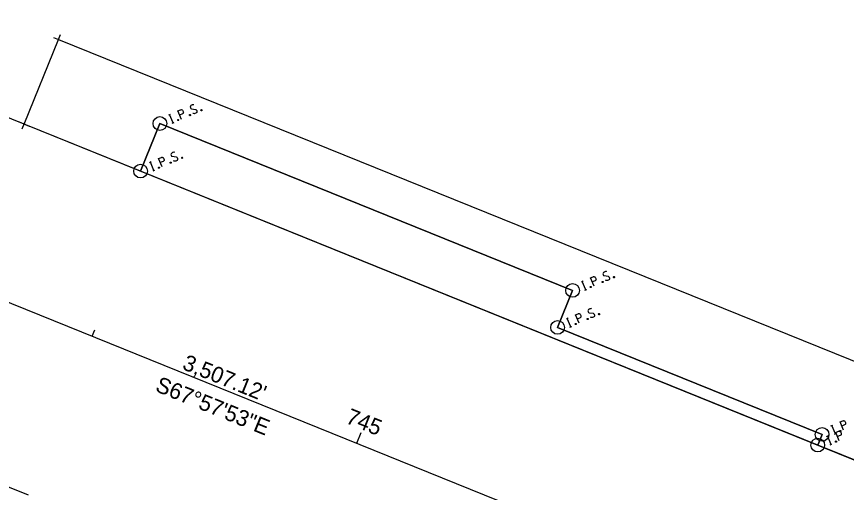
# Model space of a CAD drawing. Extents: x 2345526 to 2352057, y 624934 to 629976.
# Drawn here: x 2347207 to 2347352.4, y 627495.5 to 627578.9 of the extents above; entities that cross this region are included whole.
import ezdxf

# ---------------------------------------------------------------- set-up
doc = ezdxf.new("R2010")
doc.units = 0
for name, color, linetype in [('DT_X_Island', 7, 'Continuous'), ('DT_X_TIN_Hull', 7, 'Continuous'), ('DT_X_Void', 7, 'Continuous'), ('DV_X_Property_Line', 7, 'Continuous'), ('RW_P_Esmt_SH', 7, 'Continuous'), ('RW_X_CL', 7, 'Continuous'), ('RW_X_CL_1000_Stations', 7, 'Continuous'), ('RW_X_CL_100_Cardinal_Points', 7, 'Continuous'), ('RW_X_CL_100_Distances', 7, 'Continuous'), ('RW_X_CL_100_Stations', 7, 'Continuous'), ('RW_X_CL_500_Cardinal_Points', 7, 'Continuous'), ('RW_X_Esmt_SH', 7, 'Continuous'), ('SC_Scratch1', 7, 'Continuous')]:
    doc.layers.add(name, color=color, linetype=linetype)

msp = doc.modelspace()

# ---------------------------------------------------------------- linework, layer by layer
at = {"layer": 'DT_X_Island'}
for p, q in [((2347228.77, 627551.81), (2347232.14, 627560.15)), ((2347232.14, 627560.15), (2347304.45, 627530.89)), ((2347347.42, 627503.78), (2347228.77, 627551.81)), ((2347304.45, 627530.89), (2347301.82, 627524.4)), ((2347301.82, 627524.4), (2347348.17, 627505.64)), ((2347348.17, 627505.64), (2347347.42, 627503.78))]:
    msp.add_line(p, q, dxfattribs=at)
at = {"layer": 'DT_X_TIN_Hull'}
for p, q in [((2347214.02, 627574.02), (2347214.73, 627575.77)), ((2347208.37, 627560.06), (2347214.38, 627574.89)), ((2347213.5, 627575.25), (2347215.25, 627574.54)), ((2347214.38, 627574.89), (2347372.89, 627510.74)), ((2347208.02, 627559.19), (2347208.73, 627560.94)), ((2347207.5, 627560.42), (2347209.25, 627559.71)), ((2347228.77, 627551.81), (2347208.37, 627560.06)), ((2347232.14, 627560.15), (2347228.77, 627551.81)), ((2347304.45, 627530.89), (2347232.14, 627560.15)), ((2347301.82, 627524.4), (2347304.45, 627530.89)), ((2347134.88, 627525.08), (2347209.04, 627495.06)), ((2347348.17, 627505.64), (2347301.82, 627524.4)), ((2347347.42, 627503.78), (2347348.17, 627505.64)), ((2347366.88, 627495.91), (2347347.42, 627503.78))]:
    msp.add_line(p, q, dxfattribs=at)
at = {"layer": 'DT_X_Void'}
for points in [[(2347235.92, 627560.88), (2347235.29, 627562.36), (2347235.78, 627562.56), (2347235.84, 627562.57), (2347235.92, 627562.58), (2347235.96, 627562.57), (2347236, 627562.56), (2347236.06, 627562.52), (2347236.12, 627562.47), (2347236.18, 627562.39), (2347236.24, 627562.25), (2347236.25, 627562.2), (2347236.26, 627562.12), (2347236.25, 627562.02), (2347236.22, 627561.97), (2347236.2, 627561.93), (2347236.16, 627561.89), (2347236.09, 627561.84), (2347235.6, 627561.64)], [(2347238.11, 627563.42), (2347238.08, 627563.44), (2347238.04, 627563.45), (2347237.93, 627563.45), (2347237.81, 627563.42), (2347237.73, 627563.39), (2347237.7, 627563.37), (2347237.58, 627563.28), (2347237.5, 627563.17), (2347237.47, 627563.04), (2347237.49, 627562.94), (2347237.52, 627562.87), (2347237.58, 627562.79), (2347237.69, 627562.74), (2347238.4, 627562.63), (2347238.47, 627562.61), (2347238.51, 627562.57), (2347238.56, 627562.51), (2347238.59, 627562.44), (2347238.61, 627562.36), (2347238.62, 627562.31), (2347238.62, 627562.25), (2347238.62, 627562.19), (2347238.61, 627562.15), (2347238.6, 627562.1), (2347238.58, 627562.06), (2347238.55, 627562.02), (2347238.52, 627562), (2347238.44, 627561.95), (2347238.29, 627561.89), (2347238.19, 627561.87), (2347238.03, 627561.9), (2347237.91, 627561.93)], [(2347239.36, 627562.57), (2347239.41, 627562.59), (2347239.45, 627562.58), (2347239.5, 627562.55), (2347239.52, 627562.49), (2347239.51, 627562.43), (2347239.49, 627562.4), (2347239.44, 627562.37), (2347239.4, 627562.38), (2347239.35, 627562.42), (2347239.33, 627562.48), (2347239.34, 627562.54), (2347239.36, 627562.57)], [(2347233.69, 627561.68), (2347234.02, 627561.81)], [(2347234.48, 627560.27), (2347233.85, 627561.74)], [(2347235.28, 627560.84), (2347235.33, 627560.86), (2347235.37, 627560.85), (2347235.42, 627560.82), (2347235.44, 627560.76), (2347235.43, 627560.7), (2347235.41, 627560.67), (2347235.36, 627560.65), (2347235.32, 627560.66), (2347235.27, 627560.69), (2347235.25, 627560.75), (2347235.26, 627560.81), (2347235.28, 627560.84)], [(2347237.35, 627561.72), (2347237.4, 627561.74), (2347237.44, 627561.73), (2347237.49, 627561.7), (2347237.51, 627561.64), (2347237.5, 627561.58), (2347237.48, 627561.54), (2347237.43, 627561.52), (2347237.39, 627561.53), (2347237.34, 627561.57), (2347237.32, 627561.62), (2347237.33, 627561.68), (2347237.35, 627561.72)], [(2347234.31, 627560.2), (2347234.64, 627560.34)], [(2347234.73, 627555.08), (2347234.7, 627555.1), (2347234.66, 627555.11), (2347234.56, 627555.1), (2347234.43, 627555.08), (2347234.35, 627555.04), (2347234.32, 627555.03), (2347234.21, 627554.94), (2347234.12, 627554.82), (2347234.09, 627554.7), (2347234.11, 627554.6), (2347234.14, 627554.53), (2347234.2, 627554.45), (2347234.32, 627554.4), (2347235.02, 627554.29), (2347235.09, 627554.26), (2347235.13, 627554.23), (2347235.18, 627554.16), (2347235.21, 627554.09), (2347235.23, 627554.02), (2347235.24, 627553.97), (2347235.24, 627553.9), (2347235.24, 627553.85), (2347235.24, 627553.81), (2347235.22, 627553.76), (2347235.2, 627553.72), (2347235.17, 627553.68), (2347235.15, 627553.66), (2347235.06, 627553.61), (2347234.92, 627553.55), (2347234.82, 627553.53), (2347234.65, 627553.56), (2347234.54, 627553.59)], [(2347230.31, 627553.33), (2347230.64, 627553.47)], [(2347232.54, 627552.54), (2347231.92, 627554.01), (2347232.4, 627554.22), (2347232.46, 627554.23), (2347232.54, 627554.24), (2347232.58, 627554.23), (2347232.62, 627554.22), (2347232.69, 627554.17), (2347232.74, 627554.13), (2347232.8, 627554.05), (2347232.86, 627553.91), (2347232.87, 627553.86), (2347232.88, 627553.78), (2347232.87, 627553.68), (2347232.85, 627553.63), (2347232.83, 627553.59), (2347232.79, 627553.55), (2347232.71, 627553.5), (2347232.22, 627553.29)], [(2347235.98, 627554.23), (2347236.03, 627554.25), (2347236.07, 627554.24), (2347236.12, 627554.21), (2347236.15, 627554.15), (2347236.13, 627554.09), (2347236.11, 627554.05), (2347236.06, 627554.03), (2347236.02, 627554.04), (2347235.97, 627554.08), (2347235.95, 627554.13), (2347235.96, 627554.19), (2347235.98, 627554.23)], [(2347231.1, 627551.93), (2347230.48, 627553.4)], [(2347231.9, 627552.5), (2347231.95, 627552.52), (2347231.99, 627552.51), (2347232.04, 627552.48), (2347232.07, 627552.42), (2347232.05, 627552.36), (2347232.03, 627552.32), (2347231.98, 627552.3), (2347231.94, 627552.31), (2347231.89, 627552.35), (2347231.87, 627552.4), (2347231.88, 627552.46), (2347231.9, 627552.5)], [(2347233.97, 627553.38), (2347234.02, 627553.4), (2347234.06, 627553.39), (2347234.11, 627553.36), (2347234.14, 627553.3), (2347234.13, 627553.24), (2347234.1, 627553.2), (2347234.05, 627553.18), (2347234.01, 627553.19), (2347233.96, 627553.22), (2347233.94, 627553.28), (2347233.95, 627553.34), (2347233.97, 627553.38)], [(2347230.94, 627551.86), (2347231.26, 627552)], [(2347308.22, 627531.62), (2347307.6, 627533.09), (2347308.08, 627533.3), (2347308.14, 627533.31), (2347308.22, 627533.31), (2347308.26, 627533.3), (2347308.3, 627533.29), (2347308.37, 627533.25), (2347308.42, 627533.21), (2347308.48, 627533.12), (2347308.54, 627532.98), (2347308.55, 627532.93), (2347308.56, 627532.86), (2347308.55, 627532.76), (2347308.53, 627532.71), (2347308.51, 627532.67), (2347308.46, 627532.62), (2347308.39, 627532.58), (2347307.9, 627532.37)], [(2347310.41, 627534.16), (2347310.38, 627534.18), (2347310.34, 627534.19), (2347310.23, 627534.18), (2347310.11, 627534.16), (2347310.03, 627534.12), (2347310, 627534.11), (2347309.88, 627534.02), (2347309.8, 627533.9), (2347309.77, 627533.78), (2347309.79, 627533.68), (2347309.82, 627533.61), (2347309.88, 627533.52), (2347309.99, 627533.48), (2347310.7, 627533.37), (2347310.77, 627533.34), (2347310.81, 627533.3), (2347310.86, 627533.24), (2347310.89, 627533.17), (2347310.91, 627533.1), (2347310.92, 627533.05), (2347310.92, 627532.98), (2347310.92, 627532.93), (2347310.92, 627532.88), (2347310.9, 627532.84), (2347310.88, 627532.8), (2347310.85, 627532.76), (2347310.82, 627532.74), (2347310.74, 627532.68), (2347310.6, 627532.62), (2347310.49, 627532.61), (2347310.33, 627532.63), (2347310.22, 627532.67)], [(2347311.66, 627533.31), (2347311.71, 627533.33), (2347311.75, 627533.32), (2347311.8, 627533.29), (2347311.82, 627533.23), (2347311.81, 627533.17), (2347311.79, 627533.13), (2347311.74, 627533.11), (2347311.7, 627533.12), (2347311.65, 627533.15), (2347311.63, 627533.21), (2347311.64, 627533.27), (2347311.66, 627533.31)], [(2347305.99, 627532.41), (2347306.32, 627532.55)], [(2347306.78, 627531.01), (2347306.16, 627532.48)], [(2347309.65, 627532.46), (2347309.7, 627532.48), (2347309.74, 627532.47), (2347309.79, 627532.43), (2347309.81, 627532.38), (2347309.8, 627532.32), (2347309.78, 627532.28), (2347309.73, 627532.26), (2347309.69, 627532.27), (2347309.64, 627532.3), (2347309.62, 627532.36), (2347309.63, 627532.42), (2347309.65, 627532.46)], [(2347306.62, 627530.94), (2347306.94, 627531.08)], [(2347307.58, 627531.58), (2347307.63, 627531.6), (2347307.67, 627531.59), (2347307.72, 627531.56), (2347307.74, 627531.5), (2347307.73, 627531.44), (2347307.71, 627531.4), (2347307.66, 627531.38), (2347307.62, 627531.39), (2347307.57, 627531.43), (2347307.55, 627531.48), (2347307.56, 627531.54), (2347307.58, 627531.58)], [(2347307.79, 627527.67), (2347307.76, 627527.69), (2347307.71, 627527.7), (2347307.61, 627527.69), (2347307.49, 627527.67), (2347307.41, 627527.63), (2347307.38, 627527.62), (2347307.26, 627527.53), (2347307.18, 627527.41), (2347307.14, 627527.29), (2347307.16, 627527.19), (2347307.19, 627527.12), (2347307.25, 627527.04), (2347307.37, 627526.99), (2347308.07, 627526.88), (2347308.14, 627526.85), (2347308.18, 627526.82), (2347308.23, 627526.75), (2347308.26, 627526.68), (2347308.28, 627526.61), (2347308.29, 627526.56), (2347308.3, 627526.49), (2347308.3, 627526.44), (2347308.29, 627526.4), (2347308.27, 627526.35), (2347308.25, 627526.31), (2347308.22, 627526.27), (2347308.2, 627526.25), (2347308.11, 627526.2), (2347307.97, 627526.14), (2347307.87, 627526.12), (2347307.7, 627526.15), (2347307.59, 627526.18)], [(2347303.37, 627525.92), (2347303.69, 627526.06)], [(2347304.15, 627524.52), (2347303.53, 627525.99)], [(2347305.59, 627525.13), (2347304.97, 627526.6), (2347305.46, 627526.81), (2347305.51, 627526.82), (2347305.59, 627526.83), (2347305.63, 627526.82), (2347305.67, 627526.81), (2347305.74, 627526.76), (2347305.79, 627526.72), (2347305.85, 627526.64), (2347305.91, 627526.5), (2347305.92, 627526.45), (2347305.93, 627526.37), (2347305.93, 627526.27), (2347305.9, 627526.22), (2347305.88, 627526.18), (2347305.84, 627526.14), (2347305.76, 627526.09), (2347305.27, 627525.88)], [(2347307.02, 627525.97), (2347307.07, 627525.99), (2347307.11, 627525.98), (2347307.16, 627525.95), (2347307.19, 627525.89), (2347307.18, 627525.83), (2347307.16, 627525.79), (2347307.11, 627525.77), (2347307.07, 627525.78), (2347307.02, 627525.81), (2347306.99, 627525.87), (2347307, 627525.93), (2347307.02, 627525.97)], [(2347309.03, 627526.82), (2347309.08, 627526.84), (2347309.12, 627526.83), (2347309.17, 627526.8), (2347309.2, 627526.74), (2347309.19, 627526.68), (2347309.17, 627526.64), (2347309.12, 627526.62), (2347309.08, 627526.63), (2347309.03, 627526.67), (2347309, 627526.72), (2347309.01, 627526.78), (2347309.03, 627526.82)], [(2347303.99, 627524.45), (2347304.32, 627524.59)], [(2347304.95, 627525.09), (2347305, 627525.11), (2347305.04, 627525.1), (2347305.09, 627525.07), (2347305.12, 627525.01), (2347305.11, 627524.95), (2347305.09, 627524.91), (2347305.04, 627524.89), (2347305, 627524.9), (2347304.95, 627524.94), (2347304.92, 627524.99), (2347304.93, 627525.05), (2347304.95, 627525.09)], [(2347349.71, 627507.16), (2347350.04, 627507.3)], [(2347350.5, 627505.76), (2347349.88, 627507.23)], [(2347351.94, 627506.37), (2347351.32, 627507.84), (2347351.8, 627508.05), (2347351.86, 627508.06), (2347351.94, 627508.07), (2347351.98, 627508.06), (2347352.02, 627508.05), (2347352.09, 627508.01), (2347352.14, 627507.96), (2347352.2, 627507.88), (2347352.26, 627507.74), (2347352.27, 627507.69), (2347352.28, 627507.61), (2347352.27, 627507.51), (2347352.25, 627507.46), (2347352.23, 627507.42), (2347352.19, 627507.38), (2347352.11, 627507.33), (2347351.62, 627507.12)], [(2347350.34, 627505.69), (2347350.66, 627505.83)], [(2347351.19, 627504.52), (2347350.57, 627505.99), (2347351.05, 627506.2), (2347351.11, 627506.21), (2347351.19, 627506.21), (2347351.23, 627506.2), (2347351.27, 627506.19), (2347351.34, 627506.15), (2347351.39, 627506.11), (2347351.45, 627506.02), (2347351.51, 627505.88), (2347351.52, 627505.83), (2347351.53, 627505.75), (2347351.52, 627505.66), (2347351.5, 627505.6), (2347351.48, 627505.57), (2347351.44, 627505.52), (2347351.36, 627505.48), (2347350.87, 627505.27)], [(2347351.3, 627506.33), (2347351.35, 627506.35), (2347351.39, 627506.34), (2347351.44, 627506.31), (2347351.47, 627506.25), (2347351.46, 627506.19), (2347351.43, 627506.16), (2347351.38, 627506.13), (2347351.34, 627506.14), (2347351.29, 627506.18), (2347351.27, 627506.24), (2347351.28, 627506.3), (2347351.3, 627506.33)], [(2347348.96, 627505.31), (2347349.29, 627505.45)], [(2347349.75, 627503.91), (2347349.13, 627505.38)], [(2347350.55, 627504.48), (2347350.6, 627504.5), (2347350.64, 627504.49), (2347350.69, 627504.46), (2347350.72, 627504.4), (2347350.7, 627504.34), (2347350.68, 627504.3), (2347350.63, 627504.28), (2347350.59, 627504.29), (2347350.54, 627504.32), (2347350.52, 627504.38), (2347350.53, 627504.44), (2347350.55, 627504.48)], [(2347349.59, 627503.84), (2347349.91, 627503.97)]]:
    msp.add_lwpolyline(points, dxfattribs=at)
for centre in [(2347232.14, 627560.15), (2347228.77, 627551.81), (2347304.45, 627530.89), (2347301.82, 627524.4), (2347348.17, 627505.64), (2347347.42, 627503.78)]:
    msp.add_circle(centre, 1.2, dxfattribs=at)
at = {"layer": 'RW_P_Esmt_SH'}
for p, q in [((2347208.37, 627560.06), (2347214.38, 627574.89)), ((2347214.38, 627574.89), (2347372.89, 627510.74))]:
    msp.add_line(p, q, dxfattribs=at)
at = {"layer": 'RW_X_CL'}
msp.add_line((2345617.75, 628171.49), (2348868.68, 626855.7), dxfattribs=at)
at = {"layer": 'RW_X_CL_100_Cardinal_Points'}
for p, q in [((2347220.29, 627522.87), (2347220.74, 627523.99)), ((2347266.64, 627504.11), (2347267.39, 627505.97))]:
    msp.add_line(p, q, dxfattribs=at)
at = {"layer": 'RW_X_CL_500_Cardinal_Points'}
msp.add_line((2347266.64, 627504.11), (2347267.39, 627505.97), dxfattribs=at)
at = {"layer": 'RW_X_Esmt_SH'}
for p, q in [((2346860.77, 627700.75), (2347555.98, 627419.37)), ((2346838.26, 627645.14), (2347209.04, 627495.06))]:
    msp.add_line(p, q, dxfattribs=at)
at = {"layer": 'SC_Scratch1'}
for p, q in [((2347228.77, 627551.81), (2347232.14, 627560.15)), ((2347232.14, 627560.15), (2347304.45, 627530.89)), ((2347304.45, 627530.89), (2347301.82, 627524.4)), ((2347301.82, 627524.4), (2347348.17, 627505.64)), ((2347348.17, 627505.64), (2347347.42, 627503.78))]:
    msp.add_line(p, q, dxfattribs=at)

# ---------------------------------------------------------------- texts
at = {"layer": 'DV_X_Property_Line'}
msp.add_text('S67°57\'53"E', height=2.8, rotation=337.9647, dxfattribs=at).set_placement((2347231.15, 627513.3))
at = {"layer": 'RW_X_CL_1000_Stations'}
msp.add_text("3,507.12'", height=2.8, rotation=337.9647, dxfattribs=at).set_placement((2347235.9, 627517.16))
at = {"layer": 'RW_X_CL_100_Cardinal_Points'}
msp.add_text('745', height=2.8, rotation=337.9647, dxfattribs=at).set_placement((2347264.54, 627507.71))
at = {"layer": 'RW_X_CL_100_Distances'}
msp.add_text("3,507.12'", height=2.8, rotation=337.9647, dxfattribs=at).set_placement((2347235.9, 627517.16))
at = {"layer": 'RW_X_CL_100_Stations'}
msp.add_text('S67°57\'53"E', height=2.8, rotation=337.9647, dxfattribs=at).set_placement((2347231.15, 627513.3))
at = {"layer": 'RW_X_CL_500_Cardinal_Points'}
msp.add_text('745', height=2.8, rotation=337.9647, dxfattribs=at).set_placement((2347264.54, 627507.71))

doc.saveas('drawing.dxf')
